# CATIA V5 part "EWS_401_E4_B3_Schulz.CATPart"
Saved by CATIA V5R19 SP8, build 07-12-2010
Part number: EWS_401_E4_B3
Material "Alu_Dark": density 2710 kg/m3, Young's modulus 7e+10 Pa, Poisson ratio 0.346, thermal expansion 2.36e-05 1/K
Bounding box of the stored display mesh (mm): x 0 to 6680.811, y 0 to 1343.86, z 0 to 6680.008
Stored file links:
  I:\Download\EWS_401_E4_B3_Schulz.CATPart
  H:\KON\1702 - Principal Place-London\Bauteil_V_MockUp-Versuche\05_Catia_Modelle\Visual Mockup\Main\1702_Visual_Mockup_main.CATProduct
  H:\KON\1702 - Principal Place-London\Bauteil_V_MockUp-Versuche\05_Catia_Modelle\Visual Mockup\Visual_Mockup_skel_02.CATPart
  C:\Seele_Catia_V5_R19\Dassault Systemes\B19\win_b64\startup\materials\German\Catalog.CATMaterial
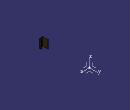
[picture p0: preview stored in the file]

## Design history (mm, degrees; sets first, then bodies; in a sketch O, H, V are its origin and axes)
Parameters
  R1 = 2.8 mm
  R2 = 3.8 mm
SheetMetalParameters1: Thickness 3, BendRadius 3.8 {= R2}, KFactor 0.350923 {= log(min(100,max(20*SheetMetalParameters1.BendRadius,SheetMetalParameters1.Thickness)/SheetMetalParameters1.Thickness))/log(100)/2}, ReliefRadialLength 1, ReliefAxialLength 2, MinimumBendRadius 0
AxisSystem1: origin (0, 0, 0), X (1, 0, 0), Y (0, 1, 0), Z (0, 0, 1)
Set1
  Plane1: linked copy from another document
  DatumCurve1: linked copy from another document
  Plane2: linked copy from another document
Body1 (main body), material "Alu_Dark"
  Sketch1 on Plane1, origin (0, 0, 5690.008), H (1, 0, 0), V (0, 1, 0)
    point P1 (6279.589, 1343.8598)
  d_Extrusion1: Extrude_Thickness 3, KFacteur 0.350923 {= log(min(100,max(20*SheetMetalParameters1.BendRadius,SheetMetalParameters1.Thickness)/SheetMetalParameters1.Thickness))/log(100)/2}, Extrude_Profile Sketch1, Extrude_StartLength 100, Extrude_EndLength 0, Extrude_StartLimit Plane2, Extrude_Radius 3.8 {= R2}, Extrude_DeductionTable SheetMetalParameters1, Extrude_FixedPoint Sketch1.P1
  d_Bend1: Bend_Thickness 3, Bend_KFactor 0.350923 {= log(min(100,max(20*d_Bend1.Bend_KFactorRadius,SheetMetalParameters1.Thickness)/SheetMetalParameters1.Thickness))/log(100)/2}, Bend_KFactorRadius 3.8 {= d_Bend1.CylindricalBendSurf_Radius}, Bend_Deduction -5.9773 {= (d_Bend1.CylindricalBendSurf_Radius+SheetMetalParameters1.Thickness*d_Bend1.Bend_KFactor)*(PI-abs(d_Bend1.BendSurf_OpenAngle))-2*(d_Bend1.CylindricalBendSurf_Radius+SheetMetalParameters1.Thickness)*tan(min((PI-abs(d_Bend1.BendSurf_OpenAngle)),(PI/2))/2)}, Bend_FirstSupport face of d_Extrusion1, Bend_SecondSupport face of d_Extrusion1
  d_Bend2: Bend_Thickness 3, Bend_BendTable SheetMetalParameters1, Bend_KFactor 0.376287 {= log(min(100,max(20*d_Bend2.Bend_KFactorRadius,SheetMetalParameters1.Thickness)/SheetMetalParameters1.Thickness))/log(100)/2}, Bend_KFactorRadius 4.8 {= d_Bend2.CylindricalBendSurf_Radius}, Bend_Deduction -6.287 {= (d_Bend2.CylindricalBendSurf_Radius+SheetMetalParameters1.Thickness*d_Bend2.Bend_KFactor)*(PI-abs(d_Bend2.BendSurf_OpenAngle))-2*(d_Bend2.CylindricalBendSurf_Radius+SheetMetalParameters1.Thickness)*tan(min((PI-abs(d_Bend2.BendSurf_OpenAngle)),(PI/2))/2)}, Bend_FirstSupport face of d_Extrusion1, Bend_SecondSupport face of d_Extrusion1
  d_Bend3: Bend_Thickness 3, Bend_BendTable SheetMetalParameters1, Bend_KFactor 0.5 {= log(min(100,max(20*d_Bend3.Bend_KFactorRadius,SheetMetalParameters1.Thickness)/SheetMetalParameters1.Thickness))/log(100)/2}, Bend_KFactorRadius 15 {= d_Bend3.CylindricalBendSurf_Radius}, Bend_Deduction -10.0819 {= (d_Bend3.CylindricalBendSurf_Radius+SheetMetalParameters1.Thickness*d_Bend3.Bend_KFactor)*(PI-abs(d_Bend3.BendSurf_OpenAngle))-2*(d_Bend3.CylindricalBendSurf_Radius+SheetMetalParameters1.Thickness)*tan(min((PI-abs(d_Bend3.BendSurf_OpenAngle)),(PI/2))/2)}, Bend_FirstSupport face of d_Extrusion1, Bend_SecondSupport face of d_Extrusion1
  d_Bend4: Bend_Thickness 3, Bend_BendTable SheetMetalParameters1, Bend_KFactor 0.350923 {= log(min(100,max(20*d_Bend4.Bend_KFactorRadius,SheetMetalParameters1.Thickness)/SheetMetalParameters1.Thickness))/log(100)/2}, Bend_KFactorRadius 3.8 {= d_Bend4.CylindricalBendSurf_Radius}, Bend_Deduction -5.9773 {= (d_Bend4.CylindricalBendSurf_Radius+SheetMetalParameters1.Thickness*d_Bend4.Bend_KFactor)*(PI-abs(d_Bend4.BendSurf_OpenAngle))-2*(d_Bend4.CylindricalBendSurf_Radius+SheetMetalParameters1.Thickness)*tan(min((PI-abs(d_Bend4.BendSurf_OpenAngle)),(PI/2))/2)}, Bend_FirstSupport face of d_Extrusion1, Bend_SecondSupport face of d_Extrusion1
  d_Bend5: Bend_Thickness 3, Bend_BendTable SheetMetalParameters1, Bend_KFactor 0.350923 {= log(min(100,max(20*d_Bend5.Bend_KFactorRadius,SheetMetalParameters1.Thickness)/SheetMetalParameters1.Thickness))/log(100)/2}, Bend_KFactorRadius 3.8 {= d_Bend5.CylindricalBendSurf_Radius}, Bend_Deduction -5.9773 {= (d_Bend5.CylindricalBendSurf_Radius+SheetMetalParameters1.Thickness*d_Bend5.Bend_KFactor)*(PI-abs(d_Bend5.BendSurf_OpenAngle))-2*(d_Bend5.CylindricalBendSurf_Radius+SheetMetalParameters1.Thickness)*tan(min((PI-abs(d_Bend5.BendSurf_OpenAngle)),(PI/2))/2)}, Bend_FirstSupport face of d_Extrusion1, Bend_SecondSupport face of d_Extrusion1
